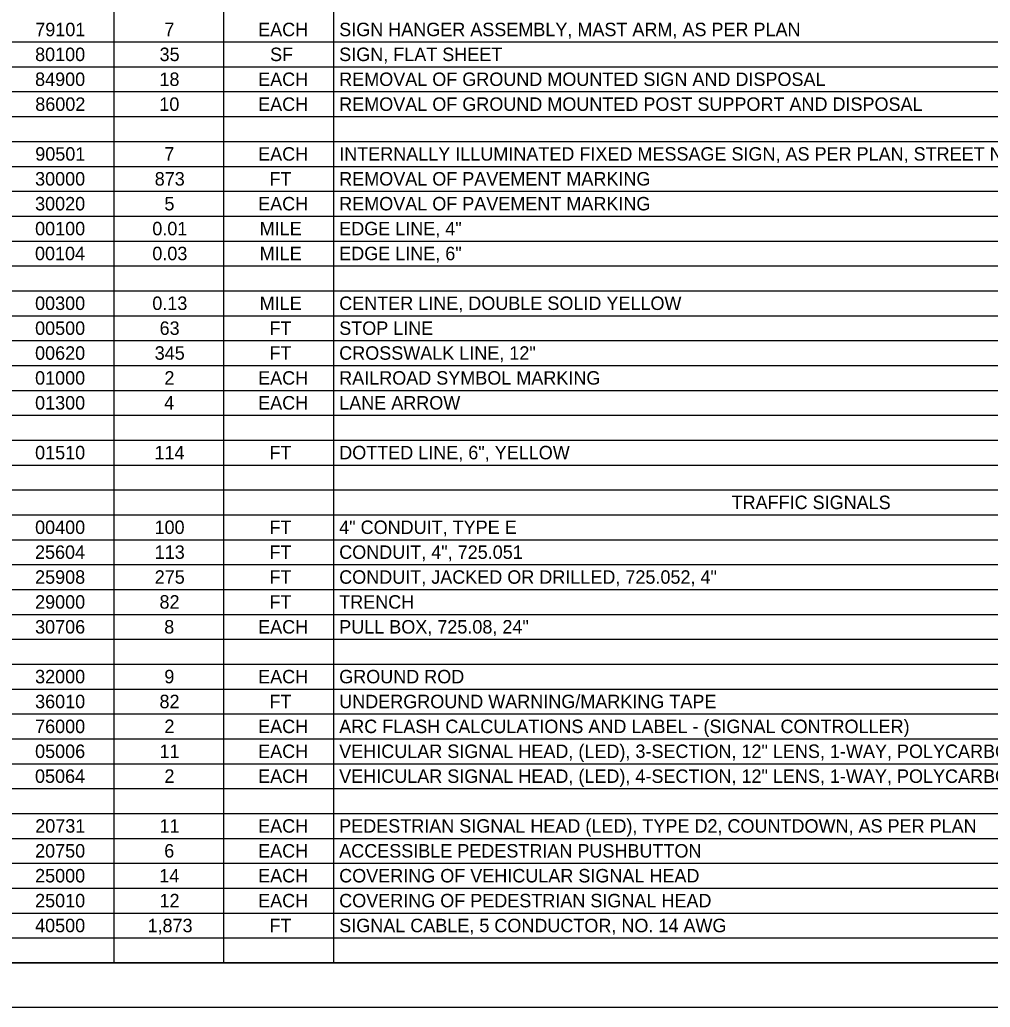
# Model space of a CAD drawing. Extents: x 0 to 34, y 0 to 22.
# Drawn here: x 16.98 to 27.9, y 0 to 11.11 of the extents above; entities that cross this region are included whole.
import ezdxf

# ---------------------------------------------------------------- set-up
doc = ezdxf.new("R2010")
doc.units = 0
for name, color, linetype in [('SH_Border', 7, 'Continuous'), ('SH_Cut_Line', 7, 'Continuous'), ('SH_Text', 7, 'Continuous')]:
    doc.layers.add(name, color=color, linetype=linetype)

msp = doc.modelspace()

# ---------------------------------------------------------------- linework, layer by layer
at = {"layer": 'SH_Border'}
msp.add_lwpolyline([(1.5, 21.5), (33.5, 21.5), (33.5, 0.5), (1.5, 0.5)], close=True, dxfattribs=at)
at = {"layer": 'SH_Cut_Line'}
msp.add_lwpolyline([(0, 0), (34, 0), (34, 22), (0, 22)], close=True, dxfattribs=at)
at = {"layer": 'SH_Text'}
for p, q in [((18.035, 21.5), (18.035, 0.5)), ((19.27, 21.5), (19.27, 0.5)), ((20.505, 21.5), (20.505, 0.5)), ((1.5, 10.86), (32, 10.86)), ((1.5, 10.58), (32, 10.58)), ((1.5, 10.3), (32, 10.3)), ((1.5, 10.02), (32, 10.02)), ((1.5, 9.74), (32, 9.74)), ((1.5, 9.46), (32, 9.46)), ((1.5, 9.18), (32, 9.18)), ((1.5, 8.9), (32, 8.9)), ((1.5, 8.62), (32, 8.62)), ((1.5, 8.34), (32, 8.34)), ((1.5, 8.06), (32, 8.06)), ((1.5, 7.78), (32, 7.78)), ((1.5, 7.5), (32, 7.5)), ((1.5, 7.22), (32, 7.22)), ((1.5, 6.94), (32, 6.94)), ((1.5, 6.66), (32, 6.66)), ((1.5, 6.38), (32, 6.38)), ((1.5, 6.1), (32, 6.1)), ((1.5, 5.82), (32, 5.82)), ((1.5, 5.54), (32, 5.54)), ((1.5, 5.26), (32, 5.26)), ((1.5, 4.98), (32, 4.98)), ((1.5, 4.7), (32, 4.7)), ((1.5, 4.42), (32, 4.42)), ((1.5, 4.14), (32, 4.14)), ((1.5, 3.86), (32, 3.86)), ((1.5, 3.58), (32, 3.58)), ((1.5, 3.3), (32, 3.3)), ((1.5, 3.02), (32, 3.02)), ((1.5, 2.74), (32, 2.74)), ((1.5, 2.46), (32, 2.46)), ((1.5, 2.18), (32, 2.18)), ((1.5, 1.9), (32, 1.9)), ((1.5, 1.62), (32, 1.62)), ((1.5, 1.34), (32, 1.34)), ((1.5, 1.06), (32, 1.06)), ((1.5, 0.78), (32, 0.78)), ((1.5, 0.5), (32, 0.5))]:
    msp.add_line(p, q, dxfattribs=at)

# ---------------------------------------------------------------- texts
for s, height, p in [('79101', 0.1515, (17.151, 10.924)), ('7', 0.152, (18.603, 10.924)), ('EACH', 0.1515, (19.659, 10.924)), ('SIGN HANGER ASSEMBLY, MAST ARM, AS PER PLAN', 0.15153, (20.571, 10.924)), ('80100', 0.1515, (17.149, 10.644)), ('35', 0.1515, (18.55, 10.644)), ('SF', 0.1515, (19.793, 10.644)), ('SIGN, FLAT SHEET', 0.15153, (20.571, 10.644)), ('84900', 0.1515, (17.149, 10.364)), ('18', 0.1515, (18.548, 10.364)), ('EACH', 0.1515, (19.659, 10.364)), ('REMOVAL OF GROUND MOUNTED SIGN AND DISPOSAL', 0.15153, (20.571, 10.364)), ('86002', 0.1515, (17.151, 10.084)), ('10', 0.1515, (18.547, 10.084)), ('EACH', 0.1515, (19.659, 10.084)), ('REMOVAL OF GROUND MOUNTED POST SUPPORT AND DISPOSAL', 0.15153, (20.571, 10.084)), ('90501', 0.1515, (17.151, 9.524)), ('7', 0.152, (18.603, 9.524)), ('EACH', 0.1515, (19.659, 9.524)), ('INTERNALLY ILLUMINATED FIXED MESSAGE SIGN, AS PER PLAN, STREET NAME SIGN', 0.15153, (20.571, 9.524)), ('30000', 0.1515, (17.149, 9.244)), ('873', 0.1515, (18.495, 9.244)), ('FT', 0.1515, (19.786, 9.244)), ('REMOVAL OF PAVEMENT MARKING', 0.15153, (20.571, 9.244)), ('30020', 0.1515, (17.149, 8.964)), ('5', 0.152, (18.604, 8.964)), ('EACH', 0.1515, (19.659, 8.964)), ('REMOVAL OF PAVEMENT MARKING', 0.15153, (20.571, 8.964)), ('00100', 0.1515, (17.149, 8.684)), ('0.01', 0.1515, (18.468, 8.684)), ('MILE', 0.1515, (19.676, 8.684)), ('EDGE LINE, 4"', 0.15153, (20.571, 8.684)), ('00104', 0.1515, (17.148, 8.404)), ('0.03', 0.1515, (18.468, 8.404)), ('MILE', 0.1515, (19.676, 8.404)), ('EDGE LINE, 6"', 0.15153, (20.571, 8.404)), ('00300', 0.1515, (17.149, 7.844)), ('0.13', 0.1515, (18.468, 7.844)), ('MILE', 0.1515, (19.676, 7.844)), ('CENTER LINE, DOUBLE SOLID YELLOW', 0.15153, (20.571, 7.844)), ('00500', 0.1515, (17.149, 7.564)), ('63', 0.1515, (18.55, 7.564)), ('FT', 0.1515, (19.786, 7.564)), ('STOP LINE', 0.1515, (20.571, 7.564)), ('00620', 0.1515, (17.149, 7.284)), ('345', 0.1515, (18.495, 7.284)), ('FT', 0.1515, (19.786, 7.284)), ('CROSSWALK LINE, 12"', 0.15153, (20.571, 7.284)), ('01000', 0.1515, (17.149, 7.004)), ('2', 0.152, (18.604, 7.004)), ('EACH', 0.1515, (19.659, 7.004)), ('RAILROAD SYMBOL MARKING', 0.15153, (20.571, 7.004)), ('01300', 0.1515, (17.149, 6.724)), ('4', 0.152, (18.601, 6.724)), ('EACH', 0.1515, (19.659, 6.724)), ('LANE ARROW', 0.1515, (20.571, 6.724)), ('01510', 0.1515, (17.149, 6.164)), ('114', 0.1515, (18.492, 6.164)), ('FT', 0.1515, (19.786, 6.164)), ('DOTTED LINE, 6", YELLOW', 0.15153, (20.571, 6.164)), ('TRAFFIC SIGNALS', 0.15153, (24.986, 5.604)), ('00400', 0.1515, (17.149, 5.324)), ('100', 0.1515, (18.493, 5.324)), ('FT', 0.1515, (19.786, 5.324)), ('4" CONDUIT, TYPE E', 0.15153, (20.571, 5.324)), ('25604', 0.1515, (17.148, 5.044)), ('113', 0.1515, (18.495, 5.044)), ('FT', 0.1515, (19.786, 5.044)), ('CONDUIT, 4", 725.051', 0.15153, (20.571, 5.044)), ('25908', 0.1515, (17.149, 4.764)), ('275', 0.1515, (18.495, 4.764)), ('FT', 0.1515, (19.786, 4.764)), ('CONDUIT, JACKED OR DRILLED, 725.052, 4"', 0.15153, (20.571, 4.764)), ('29000', 0.1515, (17.149, 4.484)), ('82', 0.1515, (18.549, 4.484)), ('FT', 0.1515, (19.786, 4.484)), ('TRENCH', 0.1515, (20.571, 4.484)), ('30706', 0.1515, (17.149, 4.204)), ('8', 0.152, (18.602, 4.204)), ('EACH', 0.1515, (19.659, 4.204)), ('PULL BOX, 725.08, 24"', 0.15153, (20.571, 4.204)), ('32000', 0.1515, (17.149, 3.644)), ('9', 0.152, (18.603, 3.644)), ('EACH', 0.1515, (19.659, 3.644)), ('GROUND ROD', 0.1515, (20.571, 3.644)), ('36010', 0.1515, (17.149, 3.364)), ('82', 0.1515, (18.549, 3.364)), ('FT', 0.1515, (19.786, 3.364)), ('UNDERGROUND WARNING/MARKING TAPE', 0.15153, (20.571, 3.364)), ('76000', 0.1515, (17.149, 3.084)), ('2', 0.152, (18.604, 3.084)), ('EACH', 0.1515, (19.659, 3.084)), ('ARC FLASH CALCULATIONS AND LABEL - (SIGNAL CONTROLLER)', 0.15153, (20.571, 3.084)), ('05006', 0.1515, (17.149, 2.804)), ('11', 0.1515, (18.549, 2.804)), ('EACH', 0.1515, (19.659, 2.804)), ('VEHICULAR SIGNAL HEAD, (LED), 3-SECTION, 12" LENS, 1-WAY, POLYCARBONATE, BLACK', 0.15153, (20.571, 2.804)), ('05064', 0.1515, (17.148, 2.524)), ('2', 0.152, (18.604, 2.524)), ('EACH', 0.1515, (19.659, 2.524)), ('VEHICULAR SIGNAL HEAD, (LED), 4-SECTION, 12" LENS, 1-WAY, POLYCARBONATE, BLACK', 0.15153, (20.571, 2.524)), ('20731', 0.1515, (17.151, 1.964)), ('11', 0.1515, (18.549, 1.964)), ('EACH', 0.1515, (19.659, 1.964)), ('PEDESTRIAN SIGNAL HEAD (LED), TYPE D2, COUNTDOWN, AS PER PLAN', 0.15153, (20.571, 1.964)), ('20750', 0.1515, (17.149, 1.684)), ('6', 0.152, (18.602, 1.684)), ('EACH', 0.1515, (19.659, 1.684)), ('ACCESSIBLE PEDESTRIAN PUSHBUTTON', 0.15153, (20.571, 1.684)), ('25000', 0.1515, (17.149, 1.404)), ('14', 0.1515, (18.546, 1.404)), ('EACH', 0.1515, (19.659, 1.404)), ('COVERING OF VEHICULAR SIGNAL HEAD', 0.15153, (20.571, 1.404)), ('25010', 0.1515, (17.149, 1.124)), ('12', 0.1515, (18.549, 1.124)), ('EACH', 0.1515, (19.659, 1.124)), ('COVERING OF PEDESTRIAN SIGNAL HEAD', 0.15153, (20.571, 1.124)), ('40500', 0.1515, (17.149, 0.844)), ('1,873', 0.1515, (18.414, 0.844)), ('FT', 0.1515, (19.786, 0.844)), ('SIGNAL CABLE, 5 CONDUCTOR, NO. 14 AWG', 0.15153, (20.571, 0.844))]:
    msp.add_text(s, height=height, dxfattribs=at).set_placement(p)

doc.saveas('drawing.dxf')
